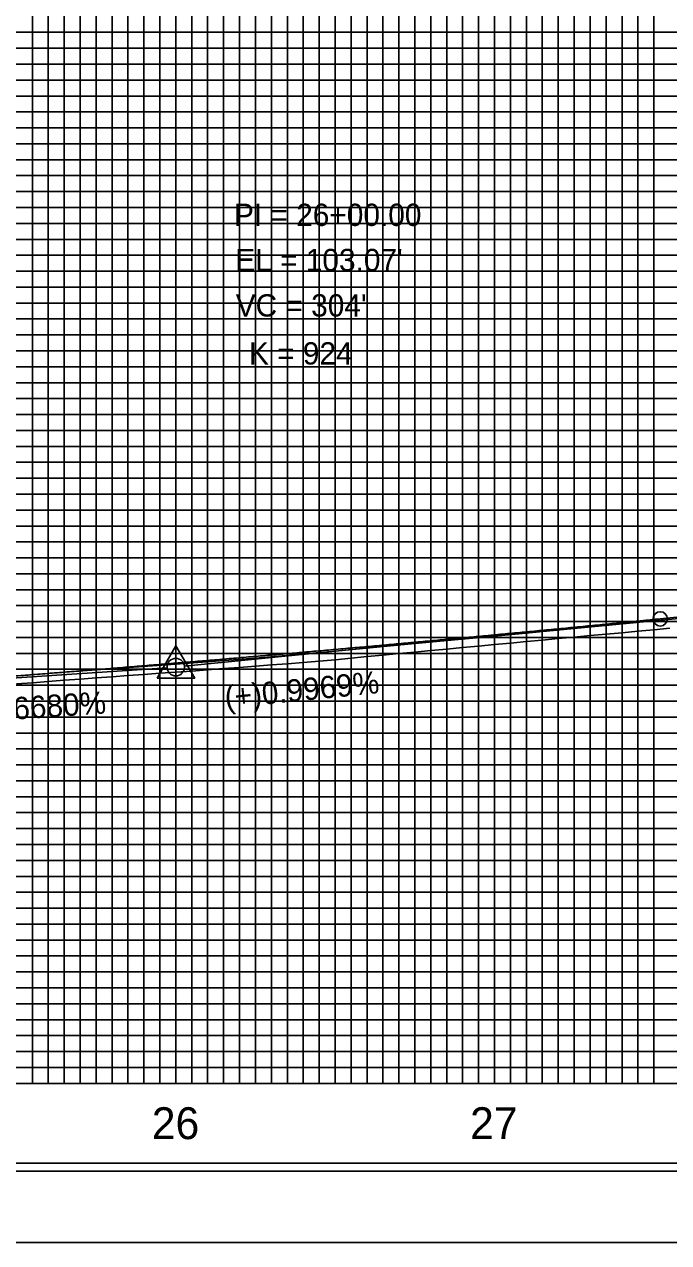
# Model space of a CAD drawing. Extents: x 2345490 to 2436403, y 465165 to 573888.
# Drawn here: x 2383319.3 to 2383521.4, y 515087.5 to 515470 of the extents above; entities that cross this region are included whole.
import ezdxf

# ---------------------------------------------------------------- set-up
doc = ezdxf.new("R2010")
doc.units = 0
for name, color, linetype in [('Old_Level_1', 7, 'Continuous'), ('Old_Level_18', 7, 'Continuous'), ('Old_Level_2', 7, 'Continuous'), ('Old_Level_41', 7, 'Continuous'), ('Old_Level_42', 7, 'Continuous'), ('Old_Level_43', 7, 'Continuous'), ('Old_Level_50', 7, 'Continuous'), ('Old_Level_51', 7, 'Continuous'), ('Old_Level_57', 7, 'Continuous'), ('Old_Level_61', 7, 'Continuous'), ('Old_Level_62', 7, 'Continuous'), ('Old_Level_63', 7, 'Continuous')]:
    doc.layers.add(name, color=color, linetype=linetype)

msp = doc.modelspace()

# ---------------------------------------------------------------- linework, layer by layer
at = {"layer": 'Old_Level_1'}
msp.add_lwpolyline([(2383316.799, 515262.941), (2383321.799, 515263.3215), (2383326.799, 515263.70025), (2383331.799, 515264.0775), (2383336.799, 515264.453), (2383341.799, 515264.81775), (2383346.799, 515265.18875), (2383351.799, 515265.5585), (2383356.799, 515265.9265), (2383361.799, 515266.29325), (2383366.799, 515266.65725), (2383371.799, 515266.99475), (2383376.799, 515267.375), (2383381.799, 515267.75425), (2383386.799, 515268.1325), (2383391.799, 515268.51), (2383396.799, 515268.8865), (2383401.799, 515269.27875), (2383406.799, 515269.65425), (2383411.799, 515270.065), (2383416.799, 515270.553), (2383421.799, 515271.04025), (2383426.799, 515271.52675), (2383431.799, 515272.0125), (2383436.799, 515272.4975), (2383441.799, 515272.9195), (2383446.799, 515273.40225), (2383451.799, 515273.88475), (2383456.799, 515274.36675), (2383461.799, 515274.8485), (2383466.799, 515275.32975), (2383471.799, 515275.74), (2383476.799, 515276.21475), (2383481.799, 515276.68925), (2383486.799, 515277.16375), (2383491.799, 515277.6385), (2383496.799, 515278.113), (2383501.799, 515278.52175), (2383506.799, 515278.99625), (2383511.799, 515279.47075), (2383516.799, 515279.94525), (2383521.799, 515280.41975)], dxfattribs=at)
at = {"layer": 'Old_Level_18'}
msp.add_lwpolyline([(2384616.79875, 516162.5265), (2383116.79875, 516162.5265), (2383116.79875, 515112.5265), (2384616.79875, 515112.5265)], close=True, dxfattribs=at)
at = {"layer": 'Old_Level_2'}
for p, q in [((2383518.799, 515283.379), (2383576.799, 515289.161)), ((2383518.799, 515283.379), (2383369.5355, 515268.49975)), ((2383214.799, 515258.073), (2383364.05525, 515268.0435))]:
    msp.add_line(p, q, dxfattribs=at)
msp.add_lwpolyline([(2383360.99325, 515264.77575), (2383372.73575, 515264.77575), (2383366.86475, 515274.9015)], close=True, dxfattribs=at)
for centre, radius in [((2383518.799, 515283.379), 2.25), ((2383366.799, 515268.22675), 2.75), ((2383366.799, 515268.22675), 2.75)]:
    msp.add_circle(centre, radius, dxfattribs=at)
msp.add_spline([(2383214.799, 515258.073), (2383220.879, 515258.48125), (2383226.959, 515258.89325), (2383233.039, 515259.3095), (2383239.119, 515259.7295), (2383245.199, 515260.15375), (2383251.279, 515260.58175), (2383257.359, 515261.014), (2383263.439, 515261.45025), (2383269.519, 515261.89025), (2383275.599, 515262.3345), (2383281.679, 515262.7825), (2383287.759, 515263.23475), (2383293.839, 515263.69075), (2383299.919, 515264.151), (2383305.999, 515264.615), (2383312.079, 515265.08325), (2383318.159, 515265.55525), (2383324.239, 515266.0315), (2383330.319, 515266.5115), (2383336.399, 515266.99575), (2383342.479, 515267.48375), (2383348.559, 515267.976), (2383354.639, 515268.472), (2383360.719, 515268.97225), (2383366.799, 515269.47625), (2383372.879, 515269.9845), (2383378.959, 515270.4965), (2383385.039, 515271.01275), (2383391.119, 515271.53275), (2383397.199, 515272.057), (2383403.279, 515272.585), (2383409.359, 515273.11725), (2383415.439, 515273.65325), (2383421.519, 515274.1935), (2383427.599, 515274.7375), (2383433.679, 515275.28575), (2383439.759, 515275.83775), (2383445.839, 515276.39375), (2383451.919, 515276.954), (2383457.999, 515277.518), (2383464.079, 515278.08625), (2383470.159, 515278.65825), (2383476.239, 515279.2345), (2383482.319, 515279.8145), (2383488.399, 515280.3985), (2383494.479, 515280.98675), (2383500.559, 515281.57875), (2383506.639, 515282.175), (2383512.719, 515282.775), (2383518.799, 515283.379)], degree=3, dxfattribs=at)
at = {"layer": 'Old_Level_41'}
msp.add_line((2384616.79875, 515137.5265), (2383116.79875, 515137.5265), dxfattribs=at)
for points in [[(2383341.79875, 516162.5265), (2383341.79875, 515137.5265), (2383391.79875, 515137.5265), (2383391.79875, 516162.5265)], [(2383366.79875, 516162.5265), (2383366.79875, 515137.5265), (2383416.79875, 515137.5265), (2383416.79875, 516162.5265)], [(2383441.79875, 516162.5265), (2383441.79875, 515137.5265), (2383491.79875, 515137.5265), (2383491.79875, 516162.5265)], [(2383466.79875, 516162.5265), (2383466.79875, 515137.5265), (2383516.79875, 515137.5265), (2383516.79875, 516162.5265)], [(2384616.79875, 515462.5265), (2383116.79875, 515462.5265), (2383116.79875, 515412.5265), (2384616.79875, 515412.5265)], [(2384616.79875, 515387.5265), (2383116.79875, 515387.5265), (2383116.79875, 515437.5265), (2384616.79875, 515437.5265)], [(2384616.79875, 515362.5265), (2383116.79875, 515362.5265), (2383116.79875, 515312.5265), (2384616.79875, 515312.5265)], [(2384616.79875, 515262.5265), (2383116.79875, 515262.5265), (2383116.79875, 515212.5265), (2384616.79875, 515212.5265)], [(2384616.79875, 515187.5265), (2383116.79875, 515187.5265), (2383116.79875, 515237.5265), (2384616.79875, 515237.5265)], [(2384616.79875, 515162.5265), (2383116.79875, 515162.5265)]]:
    msp.add_lwpolyline(points, dxfattribs=at)
at = {"layer": 'Old_Level_42'}
msp.add_lwpolyline([(2384616.79875, 515287.5265), (2383116.79875, 515287.5265), (2383116.79875, 515337.5265), (2384616.79875, 515337.5265)], dxfattribs=at)
at = {"layer": 'Old_Level_43'}
for points in [[(2383321.79875, 516162.5265), (2383321.79875, 515137.5265), (2383326.79875, 515137.5265), (2383326.79875, 516162.5265)], [(2383331.79875, 515137.5265), (2383336.79875, 515137.5265), (2383336.79875, 516162.5265)], [(2383331.79875, 516162.5265), (2383331.79875, 515137.5265)], [(2383346.79875, 516162.5265), (2383346.79875, 515137.5265), (2383351.79875, 515137.5265), (2383351.79875, 516162.5265)], [(2383356.79875, 516162.5265), (2383356.79875, 515137.5265), (2383361.79875, 515137.5265), (2383361.79875, 516162.5265)], [(2383371.79875, 516162.5265), (2383371.79875, 515137.5265), (2383376.79875, 515137.5265), (2383376.79875, 516162.5265)], [(2383381.79875, 516162.5265), (2383381.79875, 515137.5265), (2383386.79875, 515137.5265), (2383386.79875, 516162.5265)], [(2383396.79875, 516162.5265), (2383396.79875, 515137.5265), (2383401.79875, 515137.5265), (2383401.79875, 516162.5265)], [(2383406.79875, 516162.5265), (2383406.79875, 515137.5265), (2383411.79875, 515137.5265), (2383411.79875, 516162.5265)], [(2383421.79875, 516162.5265), (2383421.79875, 515137.5265), (2383426.79875, 515137.5265), (2383426.79875, 516162.5265)], [(2383431.79875, 516162.5265), (2383431.79875, 515137.5265), (2383436.79875, 515137.5265), (2383436.79875, 516162.5265)], [(2383446.79875, 516162.5265), (2383446.79875, 515137.5265), (2383451.79875, 515137.5265), (2383451.79875, 516162.5265)], [(2383456.79875, 516162.5265), (2383456.79875, 515137.5265), (2383461.79875, 515137.5265), (2383461.79875, 516162.5265)], [(2383471.79875, 516162.5265), (2383471.79875, 515137.5265), (2383476.79875, 515137.5265), (2383476.79875, 516162.5265)], [(2383481.79875, 516162.5265), (2383481.79875, 515137.5265), (2383486.79875, 515137.5265), (2383486.79875, 516162.5265)], [(2383496.79875, 516162.5265), (2383496.79875, 515137.5265), (2383511.79875, 515137.5265), (2383511.79875, 516162.5265)], [(2383501.79875, 516162.5265), (2383501.79875, 515137.5265), (2383506.79875, 515137.5265), (2383506.79875, 516162.5265)], [(2383501.79875, 516161.9265), (2383501.79875, 515137.5265), (2383506.79875, 515137.5265), (2383506.79875, 516161.9265)], [(2384566.79875, 515467.5265), (2383166.79875, 515467.5265), (2383166.79875, 515457.5265), (2384566.79875, 515457.5265)], [(2384566.79875, 515452.5265), (2383166.79875, 515452.5265), (2383166.79875, 515447.5265), (2384566.79875, 515447.5265)], [(2384566.79875, 515442.5265), (2383166.79875, 515442.5265), (2383166.79875, 515432.5265), (2384566.79875, 515432.5265)], [(2384566.79875, 515427.5265), (2383166.79875, 515427.5265), (2383166.79875, 515422.5265), (2384566.79875, 515422.5265)], [(2384566.79875, 515417.5265), (2383166.79875, 515417.5265), (2383166.79875, 515407.5265), (2384566.79875, 515407.5265)], [(2384566.79875, 515402.5265), (2383166.79875, 515402.5265), (2383166.79875, 515397.5265), (2384566.79875, 515397.5265)], [(2384566.79875, 515392.5265), (2383166.79875, 515392.5265), (2383166.79875, 515382.5265), (2384566.79875, 515382.5265)], [(2384566.79875, 515377.5265), (2383166.79875, 515377.5265), (2383166.79875, 515372.5265), (2384566.79875, 515372.5265)], [(2384566.79875, 515367.5265), (2383166.79875, 515367.5265), (2383166.79875, 515357.5265), (2384566.79875, 515357.5265)], [(2384566.79875, 515352.5265), (2383166.79875, 515352.5265), (2383166.79875, 515347.5265), (2384566.79875, 515347.5265)], [(2384566.79875, 515342.5265), (2383166.79875, 515342.5265)], [(2383166.79875, 515332.5265), (2384566.79875, 515332.5265)], [(2384566.79875, 515327.5265), (2383166.79875, 515327.5265), (2383166.79875, 515322.5265), (2384566.79875, 515322.5265)], [(2384566.79875, 515317.5265), (2383166.79875, 515317.5265)], [(2383166.79875, 515307.5265), (2384566.79875, 515307.5265)], [(2384566.79875, 515302.5265), (2383166.79875, 515302.5265), (2383166.79875, 515297.5265), (2384566.79875, 515297.5265)], [(2384566.79875, 515292.5265), (2383166.79875, 515292.5265), (2383166.79875, 515282.5265), (2384566.79875, 515282.5265)], [(2384566.79875, 515277.5265), (2383166.79875, 515277.5265), (2383166.79875, 515272.5265), (2384566.79875, 515272.5265)], [(2384566.79875, 515267.5265), (2383166.79875, 515267.5265), (2383166.79875, 515257.5265), (2384566.79875, 515257.5265)], [(2384566.79875, 515252.5265), (2383166.79875, 515252.5265), (2383166.79875, 515247.5265), (2384566.79875, 515247.5265)], [(2384566.79875, 515242.5265), (2383166.79875, 515242.5265), (2383166.79875, 515232.5265), (2384566.79875, 515232.5265)], [(2384566.79875, 515227.5265), (2383166.79875, 515227.5265), (2383166.79875, 515222.5265), (2384566.79875, 515222.5265)], [(2384566.79875, 515217.5265), (2383166.79875, 515217.5265), (2383166.79875, 515207.5265), (2384566.79875, 515207.5265)], [(2384566.79875, 515202.5265), (2383166.79875, 515202.5265), (2383166.79875, 515197.5265), (2384566.79875, 515197.5265)], [(2384566.79875, 515192.5265), (2383166.79875, 515192.5265), (2383166.79875, 515182.5265), (2384566.79875, 515182.5265)], [(2384566.79875, 515177.5265), (2383166.79875, 515177.5265), (2383166.79875, 515172.5265), (2384566.79875, 515172.5265)], [(2384566.79875, 515167.5265), (2383166.79875, 515167.5265), (2383166.79875, 515157.5265), (2384566.79875, 515157.5265)], [(2384566.79875, 515152.5265), (2383166.79875, 515152.5265), (2383166.79875, 515147.5265), (2384566.79875, 515147.5265)], [(2384566.79875, 515142.5265), (2383166.79875, 515142.5265)]]:
    msp.add_lwpolyline(points, dxfattribs=at)
at = {"layer": 'Old_Level_50'}
msp.add_lwpolyline([(2384629.29875, 516165.0765), (2382962.79875, 516165.0765), (2382962.79875, 515109.9765), (2384629.29875, 515109.9765)], close=True, dxfattribs=at)
at = {"layer": 'Old_Level_51'}
msp.add_lwpolyline([(2384633.79875, 516187.5265), (2382949.79875, 516187.5265), (2382949.79875, 515087.5265), (2384633.79875, 515087.5265)], close=True, dxfattribs=at)
at = {"layer": 'Old_Level_57'}
for p, q in [((2383366.79875, 515137.52675), (2383366.79875, 515537.52675)), ((2383366.79875, 515137.62675), (2383366.79875, 515537.52675)), ((2383466.79875, 515137.52675), (2383466.79875, 515537.52675)), ((2383466.79875, 515137.62675), (2383466.79875, 515537.52675)), ((2381716.79925, 515437.52675), (2386366.79875, 515437.52675)), ((2381716.79925, 515387.52675), (2386366.79875, 515387.52675)), ((2381716.79925, 515337.52675), (2386366.79875, 515337.52675)), ((2381716.79925, 515287.52675), (2386366.79875, 515287.52675)), ((2381716.79925, 515237.52675), (2386366.79875, 515237.52675)), ((2381716.799, 515187.52675), (2386366.79875, 515187.52675)), ((2381716.79925, 515137.52675), (2386366.79875, 515137.52675))]:
    msp.add_line(p, q, dxfattribs=at)
at = {"layer": 'Old_Level_61'}
msp.add_lwpolyline([(2383016.799, 515245.09425), (2383041.799, 515246.658), (2383066.799, 515248.3365), (2383091.799, 515249.96375), (2383116.799, 515251.56325), (2383141.799, 515253.174), (2383166.799, 515254.73025), (2383191.799, 515256.2415), (2383216.799, 515257.7695), (2383241.799, 515259.618), (2383266.799, 515261.59875), (2383291.799, 515263.534), (2383316.799, 515265.44125), (2383341.799, 515267.33025), (2383366.799, 515269.1755), (2383391.799, 515271.07625), (2383416.799, 515273.18275), (2383441.799, 515275.62975), (2383466.799, 515277.967), (2383491.799, 515280.3285), (2383516.799, 515282.71575), (2383541.799, 515285.099)], dxfattribs=at)
at = {"layer": 'Old_Level_63'}
msp.add_line((2381766.79875, 515137.5265), (2386228.05125, 515137.5265), dxfattribs=at)

# ---------------------------------------------------------------- texts
at = {"layer": 'Old_Level_2'}
for s, height, p in [('PI = 26+00.00', 7.0000005, (2383385.05925, 515406.72475)), ("EL = 103.07'", 7.0000005, (2383385.4745, 515392.53875)), ("VC = 304'", 7.000001, (2383385.60225, 515378.29275)), ('K = 924', 7.000001, (2383389.754, 515363.224))]:
    msp.add_text(s, height=height, dxfattribs=at).set_placement(p)
for s, rotation, p in [('(+)0.9969%', 5.6928639, (2383382.493, 515255.262)), ('(+)0.6680%', 3.8216806, (2383296.568, 515250.434))]:
    msp.add_text(s, height=7.000001, rotation=rotation, dxfattribs=at).set_placement(p)
at = {"layer": 'Old_Level_62'}
for s, p in [('26', (2383359.284, 515120.0265)), ('27', (2383459.1415, 515120.0265))]:
    msp.add_text(s, height=10.000001, dxfattribs=at).set_placement(p)

doc.saveas('drawing.dxf')
